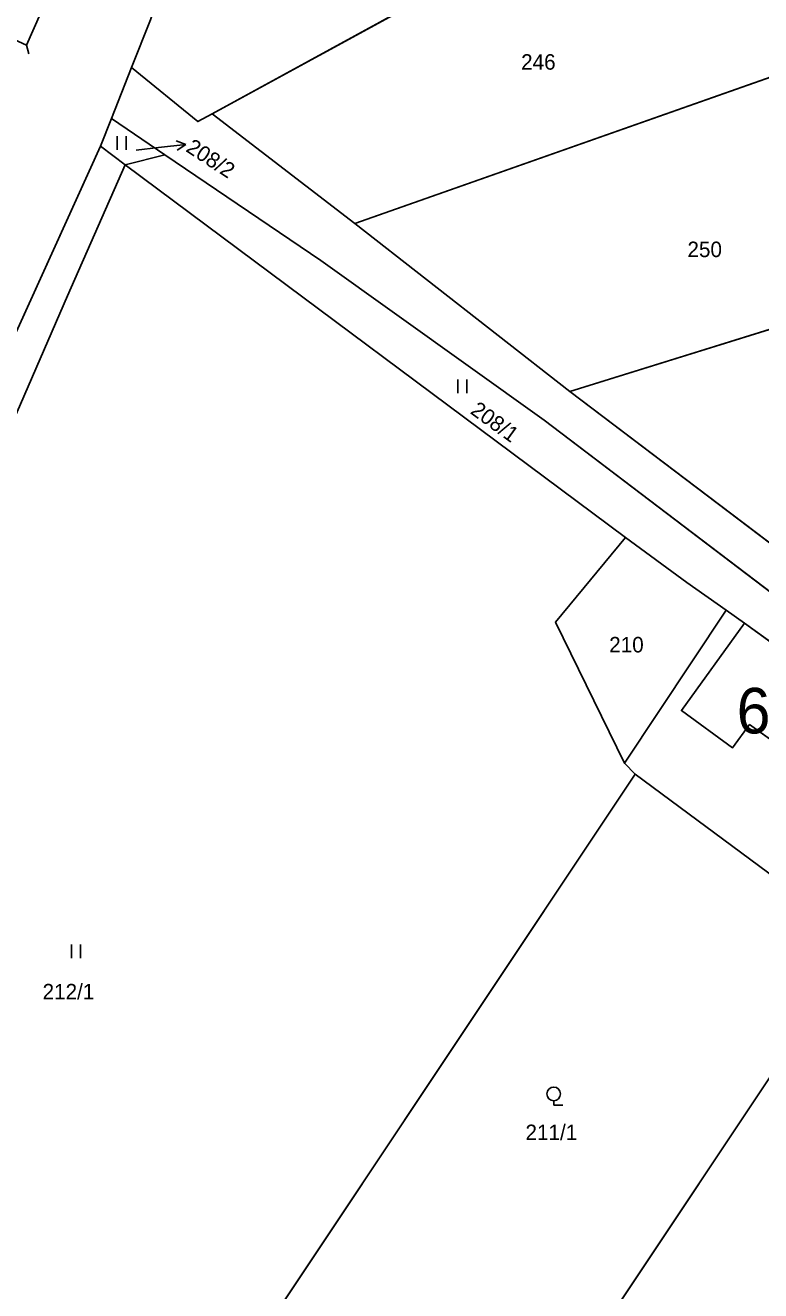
# Model space of a CAD drawing. Extents: x -689422 to -685210, y -987725 to -982160.
# Drawn here: x -686325.7 to -686244.8, y -986937.7 to -986798.7 of the extents above; entities that cross this region are included whole.
import ezdxf

# ---------------------------------------------------------------- set-up
doc = ezdxf.new("R2010")
doc.units = 0
for name, color, linetype in [('KN_Budovy', 7, 'Continuous'), ('KN_Budovy_cisla_domovni', 7, 'Continuous'), ('KN_Hranice_parcel', 7, 'Continuous'), ('KN_Hranice_parcel_vnitrni_kresba', 7, 'Continuous'), ('KN_Parcelni cisla', 7, 'Continuous'), ('KN_Parcelni cisla_sipky', 7, 'Continuous'), ('KN_Polygon parcely', 7, 'Continuous'), ('KN_POZEMKY_ORNA PUDA', 7, 'Continuous'), ('KN_POZEMKY_OSTATNI PLOCHA', 7, 'Continuous'), ('KN_POZEMKY_OVOCNY_SAD', 7, 'Continuous'), ('KN_POZEMKY_TTP', 7, 'Continuous'), ('KN_POZEMKY_ZASTAVENA PLOCHA', 7, 'Continuous'), ('KN_VYUZITI_14_ostatni plocha_dráha', 7, 'Continuous'), ('KN_VYUZITI_17_ostatni plocha_ostatni komunikace', 7, 'Continuous'), ('KN_Značky kultur', 7, 'Continuous')]:
    doc.layers.add(name, color=color, linetype=linetype)

msp = doc.modelspace()

# ---------------------------------------------------------------- linework, layer by layer
at = {"layer": 'KN_Budovy'}
msp.add_lwpolyline([(-686246.61, -986864.37), (-686253.56, -986873.99), (-686247.92, -986878.07), (-686246.06, -986875.53), (-686235.76, -986882.89), (-686230.77, -986875.91), (-686234.63, -986873.1), (-686233.85, -986872.02), (-686235.19, -986871.05), (-686235.97, -986872.12)], close=True, dxfattribs=at)
at = {"layer": 'KN_Hranice_parcel'}
for p, q in [((-686248.65, -986777.52), (-686305.13, -986808.42)), ((-686289.44, -986820.47), (-686236.51, -986801.84)), ((-686313.98, -986803.35), (-686316.2, -986808.94)), ((-686316.2, -986808.94), (-686317.41, -986811.99)), ((-686310.32, -986812.92), (-686316.2, -986808.94)), ((-686289.44, -986820.47), (-686305.13, -986808.42)), ((-686317.41, -986811.99), (-686314.68, -986814.02)), ((-686310.32, -986812.92), (-686314.68, -986814.02)), ((-686314.68, -986814.02), (-686321.02, -986828.44)), ((-686314.68, -986814.02), (-686259.69, -986854.96)), ((-686265.83, -986838.92), (-686289.44, -986820.47)), ((-686265.83, -986838.92), (-686224.06, -986825.97)), ((-686235.69, -986861.76), (-686265.83, -986838.92)), ((-686252.94, -986859.92), (-686259.69, -986854.96)), ((-686248.62, -986862.96), (-686252.94, -986859.92)), ((-686248.62, -986862.96), (-686259.81, -986879.78)), ((-686246.61, -986864.37), (-686248.62, -986862.96)), ((-686259.81, -986879.78), (-686258.63, -986880.97)), ((-686240.57, -986909.38), (-686276.46, -986963.21))]:
    msp.add_line(p, q, dxfattribs=at)
for points in [[(-686313.98, -986803.35), (-686311.89, -986798.09), (-686298.36, -986758.45), (-686273.39, -986672.53)], [(-686305.13, -986808.42), (-686306.71, -986809.28), (-686313.98, -986803.35)], [(-686317.41, -986811.99), (-686334.55, -986849.71), (-686362.97, -986907.55), (-686386.12, -986948.49), (-686392.99, -986959.3)], [(-686221.36, -986878.58), (-686239.16, -986864.48), (-686268.63, -986842.1), (-686293.19, -986824.53), (-686310.32, -986812.92)], [(-686321.02, -986828.44), (-686328.35, -986845.32), (-686339.13, -986869.1), (-686360.33, -986909.46), (-686369.53, -986927.01), (-686373.84, -986934.54), (-686383.6, -986950.14), (-686390.19, -986960.5)], [(-686259.69, -986854.96), (-686267.39, -986864.26), (-686259.81, -986879.78)], [(-686230.77, -986875.91), (-686234.63, -986873.1), (-686233.85, -986872.02), (-686235.19, -986871.05), (-686235.97, -986872.12), (-686246.61, -986864.37)], [(-686276.46, -986963.21), (-686309.38, -986957.06), (-686258.63, -986880.97)], [(-686258.63, -986880.97), (-686243.11, -986892.46), (-686235.76, -986882.89)]]:
    msp.add_lwpolyline(points, dxfattribs=at)
at = {"layer": 'KN_Hranice_parcel_vnitrni_kresba'}
for p, q in [((-686325.52, -986800.87), (-686324.01, -986797.41)), ((-686330.17, -986798.8), (-686325.52, -986800.87)), ((-686325.28, -986801.84), (-686325.52, -986800.87)), ((-686253.56, -986873.99), (-686246.61, -986864.37)), ((-686253.56, -986873.99), (-686247.92, -986878.07)), ((-686247.92, -986878.07), (-686246.06, -986875.53)), ((-686246.06, -986875.53), (-686235.76, -986882.89))]:
    msp.add_line(p, q, dxfattribs=at)
at = {"layer": 'KN_Parcelni cisla_sipky'}
for p, q in [((-686313.5, -986812.41), (-686311.02, -986812.12)), ((-686311.02, -986812.12), (-686308.04, -986811.81)), ((-686308.04, -986811.81), (-686309.08, -986811.41)), ((-686308.04, -986811.81), (-686308.98, -986812.41))]:
    msp.add_line(p, q, dxfattribs=at)
at = {"layer": 'KN_Polygon parcely'}
for points in [[(-686334.55, -986849.71), (-686317.41, -986811.99), (-686316.2, -986808.94), (-686313.98, -986803.35), (-686311.89, -986798.09), (-686298.36, -986758.45), (-686273.39, -986672.53), (-686271.11, -986668.04), (-686267.2, -986660.35), (-686263.56, -986653.17), (-686269.65, -986644.35), (-686269.44, -986643.68), (-686268.17, -986639.64), (-686261.88, -986619.46), (-686254.49, -986614.18), (-686248.98, -986597.43), (-686248.87, -986597.1), (-686230.95, -986542.68), (-686226.18, -986528.63), (-686222.26, -986514.82), (-686214.08, -986486.02)], [(-686235.69, -986861.76), (-686265.83, -986838.92), (-686289.44, -986820.47), (-686305.13, -986808.42), (-686306.71, -986809.28), (-686313.98, -986803.35), (-686316.2, -986808.94), (-686310.32, -986812.92), (-686293.19, -986824.53), (-686268.63, -986842.1), (-686239.16, -986864.48)]]:
    msp.add_lwpolyline(points, dxfattribs=at)
for points in [[(-686225.85, -986765.23), (-686273.39, -986672.53), (-686298.36, -986758.45), (-686311.89, -986798.09), (-686313.98, -986803.35), (-686306.71, -986809.28), (-686305.13, -986808.42), (-686248.65, -986777.52)], [(-686305.13, -986808.42), (-686289.44, -986820.47), (-686236.51, -986801.84), (-686248.65, -986777.52)], [(-686265.83, -986838.92), (-686224.06, -986825.97), (-686236.51, -986801.84), (-686289.44, -986820.47)], [(-686316.2, -986808.94), (-686317.41, -986811.99), (-686314.68, -986814.02), (-686310.32, -986812.92)], [(-686386.12, -986948.49), (-686392.99, -986959.3), (-686390.19, -986960.5), (-686383.6, -986950.14), (-686373.84, -986934.54), (-686369.53, -986927.01), (-686360.33, -986909.46), (-686339.13, -986869.1), (-686328.35, -986845.32), (-686321.02, -986828.44), (-686314.68, -986814.02), (-686317.41, -986811.99), (-686334.55, -986849.71), (-686362.97, -986907.55)], [(-686268.63, -986842.1), (-686293.19, -986824.53), (-686310.32, -986812.92), (-686314.68, -986814.02), (-686259.69, -986854.96), (-686252.94, -986859.92), (-686248.62, -986862.96), (-686246.61, -986864.37), (-686235.97, -986872.12), (-686235.19, -986871.05), (-686233.85, -986872.02), (-686234.63, -986873.1), (-686230.77, -986875.91), (-686223.22, -986881.4), (-686221.36, -986878.58), (-686239.16, -986864.48)], [(-686276.46, -986963.21), (-686309.38, -986957.06), (-686258.63, -986880.97), (-686259.81, -986879.78), (-686267.39, -986864.26), (-686259.69, -986854.96), (-686314.68, -986814.02), (-686321.02, -986828.44), (-686328.35, -986845.32), (-686339.13, -986869.1), (-686360.33, -986909.46), (-686369.53, -986927.01), (-686373.84, -986934.54), (-686383.6, -986950.14), (-686390.19, -986960.5), (-686388.26, -986961.33), (-686266.07, -987013.62), (-686241.72, -986968.36)], [(-686231.93, -986859.96), (-686211.89, -986850.33), (-686224.06, -986825.97), (-686265.83, -986838.92), (-686235.69, -986861.76), (-686233.04, -986860.49)], [(-686248.62, -986862.96), (-686252.94, -986859.92), (-686259.69, -986854.96), (-686267.39, -986864.26), (-686259.81, -986879.78)], [(-686243.11, -986892.46), (-686235.76, -986882.89), (-686230.77, -986875.91), (-686234.63, -986873.1), (-686233.85, -986872.02), (-686235.19, -986871.05), (-686235.97, -986872.12), (-686246.61, -986864.37), (-686248.62, -986862.96), (-686259.81, -986879.78), (-686258.63, -986880.97)], [(-686232.81, -986895.96), (-686223.22, -986881.4), (-686230.77, -986875.91), (-686235.76, -986882.89), (-686243.11, -986892.46), (-686258.63, -986880.97), (-686309.38, -986957.06), (-686276.46, -986963.21), (-686240.57, -986909.38), (-686241.25, -986908.85), (-686238.18, -986904.17)], [(-686223.87, -986922.48), (-686240.57, -986909.38), (-686276.46, -986963.21), (-686241.72, -986968.36), (-686216.07, -986928.72)]]:
    msp.add_lwpolyline(points, close=True, dxfattribs=at)
at = {"layer": 'KN_POZEMKY_ORNA PUDA'}
for p, q in [((-686305.13, -986808.42), (-686248.65, -986777.52)), ((-686236.51, -986801.84), (-686289.44, -986820.47)), ((-686289.44, -986820.47), (-686236.51, -986801.84)), ((-686289.44, -986820.47), (-686305.13, -986808.42)), ((-686265.83, -986838.92), (-686289.44, -986820.47)), ((-686265.83, -986838.92), (-686224.06, -986825.97)), ((-686224.06, -986825.97), (-686265.83, -986838.92)), ((-686235.69, -986861.76), (-686265.83, -986838.92)), ((-686267.39, -986864.26), (-686259.69, -986854.96)), ((-686259.69, -986854.96), (-686252.94, -986859.92)), ((-686252.94, -986859.92), (-686248.62, -986862.96)), ((-686248.62, -986862.96), (-686259.81, -986879.78)), ((-686259.81, -986879.78), (-686267.39, -986864.26)), ((-686276.46, -986963.21), (-686240.57, -986909.38))]:
    msp.add_line(p, q, dxfattribs=at)
at = {"layer": 'KN_POZEMKY_OSTATNI PLOCHA'}
for p, q in [((-686311.89, -986798.09), (-686313.98, -986803.35)), ((-686313.98, -986803.35), (-686316.2, -986808.94)), ((-686316.2, -986808.94), (-686313.98, -986803.35)), ((-686313.98, -986803.35), (-686306.71, -986809.28)), ((-686316.2, -986808.94), (-686317.41, -986811.99)), ((-686310.32, -986812.92), (-686316.2, -986808.94)), ((-686306.71, -986809.28), (-686305.13, -986808.42)), ((-686305.13, -986808.42), (-686289.44, -986820.47)), ((-686317.41, -986811.99), (-686334.55, -986849.71)), ((-686293.19, -986824.53), (-686310.32, -986812.92)), ((-686289.44, -986820.47), (-686265.83, -986838.92)), ((-686268.63, -986842.1), (-686293.19, -986824.53)), ((-686265.83, -986838.92), (-686235.69, -986861.76)), ((-686239.16, -986864.48), (-686268.63, -986842.1))]:
    msp.add_line(p, q, dxfattribs=at)
at = {"layer": 'KN_POZEMKY_OVOCNY_SAD'}
for p, q in [((-686309.38, -986957.06), (-686258.63, -986880.97)), ((-686258.63, -986880.97), (-686243.11, -986892.46)), ((-686240.57, -986909.38), (-686276.46, -986963.21))]:
    msp.add_line(p, q, dxfattribs=at)
at = {"layer": 'KN_POZEMKY_TTP'}
for p, q in [((-686248.65, -986777.52), (-686305.13, -986808.42)), ((-686313.98, -986803.35), (-686311.89, -986798.09)), ((-686306.71, -986809.28), (-686313.98, -986803.35)), ((-686317.41, -986811.99), (-686316.2, -986808.94)), ((-686316.2, -986808.94), (-686310.32, -986812.92)), ((-686305.13, -986808.42), (-686306.71, -986809.28)), ((-686334.55, -986849.71), (-686317.41, -986811.99)), ((-686314.68, -986814.02), (-686317.41, -986811.99)), ((-686317.41, -986811.99), (-686314.68, -986814.02)), ((-686314.68, -986814.02), (-686310.32, -986812.92)), ((-686310.32, -986812.92), (-686314.68, -986814.02)), ((-686310.32, -986812.92), (-686293.19, -986824.53)), ((-686321.02, -986828.44), (-686314.68, -986814.02)), ((-686314.68, -986814.02), (-686321.02, -986828.44)), ((-686259.69, -986854.96), (-686314.68, -986814.02)), ((-686314.68, -986814.02), (-686259.69, -986854.96)), ((-686293.19, -986824.53), (-686268.63, -986842.1)), ((-686328.35, -986845.32), (-686321.02, -986828.44)), ((-686321.02, -986828.44), (-686328.35, -986845.32)), ((-686268.63, -986842.1), (-686239.16, -986864.48)), ((-686259.69, -986854.96), (-686267.39, -986864.26)), ((-686252.94, -986859.92), (-686259.69, -986854.96)), ((-686248.62, -986862.96), (-686252.94, -986859.92)), ((-686246.61, -986864.37), (-686248.62, -986862.96)), ((-686267.39, -986864.26), (-686259.81, -986879.78)), ((-686235.97, -986872.12), (-686246.61, -986864.37)), ((-686259.81, -986879.78), (-686258.63, -986880.97)), ((-686258.63, -986880.97), (-686309.38, -986957.06))]:
    msp.add_line(p, q, dxfattribs=at)
at = {"layer": 'KN_POZEMKY_ZASTAVENA PLOCHA'}
for p, q in [((-686259.81, -986879.78), (-686248.62, -986862.96)), ((-686248.62, -986862.96), (-686246.61, -986864.37)), ((-686246.61, -986864.37), (-686235.97, -986872.12)), ((-686258.63, -986880.97), (-686259.81, -986879.78)), ((-686243.11, -986892.46), (-686258.63, -986880.97))]:
    msp.add_line(p, q, dxfattribs=at)
at = {"layer": 'KN_VYUZITI_14_ostatni plocha_dráha'}
for p, q in [((-686311.89, -986798.09), (-686313.98, -986803.35)), ((-686313.98, -986803.35), (-686316.2, -986808.94)), ((-686316.2, -986808.94), (-686317.41, -986811.99)), ((-686317.41, -986811.99), (-686334.55, -986849.71))]:
    msp.add_line(p, q, dxfattribs=at)
at = {"layer": 'KN_VYUZITI_17_ostatni plocha_ostatni komunikace'}
for p, q in [((-686316.2, -986808.94), (-686313.98, -986803.35)), ((-686313.98, -986803.35), (-686306.71, -986809.28)), ((-686310.32, -986812.92), (-686316.2, -986808.94)), ((-686306.71, -986809.28), (-686305.13, -986808.42)), ((-686305.13, -986808.42), (-686289.44, -986820.47)), ((-686293.19, -986824.53), (-686310.32, -986812.92)), ((-686289.44, -986820.47), (-686265.83, -986838.92)), ((-686268.63, -986842.1), (-686293.19, -986824.53)), ((-686265.83, -986838.92), (-686235.69, -986861.76)), ((-686239.16, -986864.48), (-686268.63, -986842.1))]:
    msp.add_line(p, q, dxfattribs=at)
at = {"layer": 'KN_Značky kultur'}
for p, q in [((-686315.58, -986812.4), (-686315.58, -986810.9)), ((-686314.58, -986812.4), (-686314.58, -986810.9)), ((-686278.13, -986839.11), (-686278.13, -986837.61)), ((-686277.13, -986839.11), (-686277.13, -986837.61)), ((-686320.6, -986901.2), (-686320.6, -986899.7)), ((-686319.6, -986901.2), (-686319.6, -986899.7)), ((-686267.59, -986916.85), (-686267.59, -986917.35)), ((-686267.59, -986917.35), (-686266.59, -986917.35))]:
    msp.add_line(p, q, dxfattribs=at)
msp.add_circle((-686267.59, -986916.1), 0.75, dxfattribs=at)

# ---------------------------------------------------------------- texts
at = {"layer": 'KN_Budovy_cisla_domovni'}
msp.add_text('61', height=5, dxfattribs=at).set_placement((-686247.48, -986876.5))
at = {"layer": 'KN_Parcelni cisla'}
for s, p in [('246', (-686271.17, -986803.58)), ('250', (-686252.89, -986824.17)), ('210', (-686261.49, -986867.6)), ('212/1', (-686323.77, -986905.72)), ('211/1', (-686270.69, -986921.18))]:
    msp.add_text(s, height=1.7, dxfattribs=at).set_placement(p)
for s, rotation, p in [('208/2', 327, (-686308.13, -986812.49)), ('208/1', 324, (-686276.86, -986841.28))]:
    msp.add_text(s, height=1.7, rotation=rotation, dxfattribs=at).set_placement(p)

doc.saveas('drawing.dxf')
